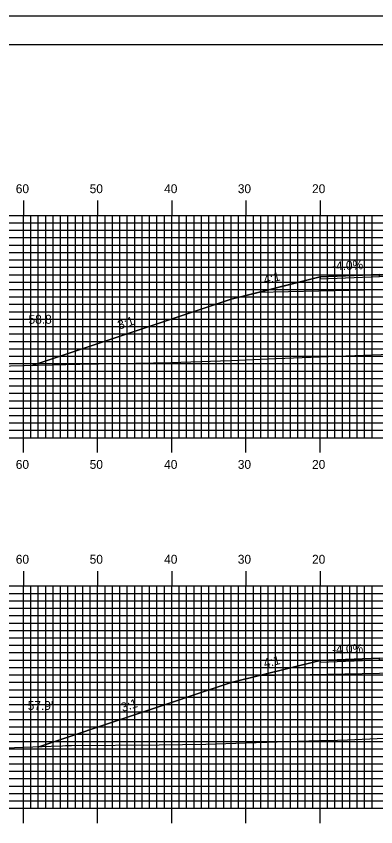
# Model space of a CAD drawing. Extents: x 1788156 to 1788500, y 442591 to 442811.
# Drawn here: x 1788261.2 to 1788309.6, y 442701.2 to 442810.5 of the extents above; entities that cross this region are included whole.
import ezdxf

# ---------------------------------------------------------------- set-up
doc = ezdxf.new("R2010")
doc.units = 0
for name, color, linetype in [('ANNOTATION', 7, 'Continuous'), ('BORDER', 7, 'Continuous'), ('D_Roadway_Centerline', 7, 'Continuous'), ('D_Roadway_Edge_Shoulder', 7, 'Continuous'), ('D_Roadway_SlopeLines', 7, 'Continuous'), ('D_Roadway_SubGrade', 7, 'Continuous'), ('D_Text_Standard', 7, 'Continuous'), ('H_V ANNOTATION', 7, 'Continuous'), ('MAJOR', 7, 'Continuous'), ('MINOR', 7, 'Continuous'), ('PLOT BOUNDARY', 7, 'Continuous'), ('S_Roadway_Centerline', 7, 'Continuous')]:
    doc.layers.add(name, color=color, linetype=linetype)

msp = doc.modelspace()

# ---------------------------------------------------------------- linework, layer by layer
at = {"layer": 'BORDER'}
msp.add_lwpolyline([(1788172.53, 442596.67), (1788492.53, 442596.67), (1788492.53, 442806.67), (1788172.53, 442806.67)], close=True, dxfattribs=at)
at = {"layer": 'D_Roadway_Centerline'}
for points in [[(1788263.31, 442763.43), (1788290.13, 442772.37), (1788293.77, 442773.28), (1788302.13, 442775.37), (1788310.13, 442775.69), (1788322.13, 442775.96), (1788334.13, 442776.22), (1788342.13, 442775.9), (1788350.49, 442773.81), (1788354.13, 442772.9), (1788371.39, 442767.15)], [(1788264.21, 442711.98), (1788290.13, 442720.62), (1788293.77, 442721.53), (1788302.13, 442723.62), (1788310.13, 442723.94), (1788322.13, 442724.21), (1788334.13, 442724.47), (1788342.13, 442724.15), (1788350.49, 442722.06), (1788354.13, 442721.15), (1788372.38, 442715.07)]]:
    msp.add_lwpolyline(points, dxfattribs=at)
at = {"layer": 'D_Roadway_Edge_Shoulder'}
for points in [[(1788310.13, 442775.69), (1788302.13, 442775.37), (1788302.13, 442775.12), (1788310.13, 442775.44)], [(1788310.13, 442723.94), (1788302.13, 442723.62), (1788302.13, 442723.37), (1788310.13, 442723.69)]]:
    msp.add_lwpolyline(points, close=True, dxfattribs=at)
at = {"layer": 'D_Roadway_SlopeLines'}
for points in [[(1788302.13, 442775.37), (1788290.13, 442772.37), (1788263.31, 442763.43)], [(1788302.13, 442723.62), (1788290.13, 442720.62), (1788264.21, 442711.98)]]:
    msp.add_lwpolyline(points, dxfattribs=at)
at = {"layer": 'D_Roadway_SubGrade'}
for points in [[(1788310.13, 442773.61), (1788293.77, 442773.28), (1788302.13, 442775.37), (1788302.13, 442775.12), (1788310.13, 442775.44), (1788322.13, 442775.71), (1788334.13, 442775.97), (1788342.13, 442775.65), (1788342.13, 442775.9), (1788350.49, 442773.81), (1788334.13, 442774.14), (1788322.13, 442773.87)], [(1788310.13, 442721.86), (1788293.77, 442721.53), (1788302.13, 442723.62), (1788302.13, 442723.37), (1788310.13, 442723.69), (1788322.13, 442723.96), (1788334.13, 442724.22), (1788342.13, 442723.9), (1788342.13, 442724.15), (1788350.49, 442722.06), (1788334.13, 442722.39), (1788322.13, 442722.12)]]:
    msp.add_lwpolyline(points, close=True, dxfattribs=at)
at = {"layer": 'MAJOR'}
for p, q in [((1788262.13, 442785.67), (1788262.13, 442783.67)), ((1788272.13, 442785.67), (1788272.13, 442783.67)), ((1788282.13, 442785.67), (1788282.13, 442783.67)), ((1788292.13, 442785.67), (1788292.13, 442783.67)), ((1788302.13, 442785.67), (1788302.13, 442783.67)), ((1788182.13, 442783.67), (1788462.13, 442783.67)), ((1788182.13, 442783.67), (1788462.13, 442783.67)), ((1788262.13, 442753.67), (1788262.13, 442783.67)), ((1788272.13, 442753.67), (1788272.13, 442783.67)), ((1788282.13, 442753.67), (1788282.13, 442783.67)), ((1788292.13, 442753.67), (1788292.13, 442783.67)), ((1788302.13, 442753.67), (1788302.13, 442783.67)), ((1788182.13, 442778.67), (1788462.13, 442778.67)), ((1788182.13, 442773.67), (1788462.13, 442773.67)), ((1788182.13, 442768.67), (1788462.13, 442768.67)), ((1788182.13, 442763.67), (1788462.13, 442763.67)), ((1788182.13, 442758.67), (1788462.13, 442758.67)), ((1788182.13, 442753.67), (1788462.13, 442753.67)), ((1788182.13, 442753.67), (1788462.13, 442753.67)), ((1788262.13, 442751.66), (1788262.13, 442753.67)), ((1788272.13, 442751.66), (1788272.13, 442753.67)), ((1788282.13, 442751.66), (1788282.13, 442753.67)), ((1788292.13, 442751.66), (1788292.13, 442753.67)), ((1788302.13, 442751.66), (1788302.13, 442753.67)), ((1788262.13, 442735.67), (1788262.13, 442733.67)), ((1788272.13, 442735.67), (1788272.13, 442733.67)), ((1788282.13, 442735.67), (1788282.13, 442733.67)), ((1788292.13, 442735.67), (1788292.13, 442733.67)), ((1788302.13, 442735.67), (1788302.13, 442733.67)), ((1788182.13, 442733.67), (1788462.13, 442733.67)), ((1788182.13, 442733.67), (1788462.13, 442733.67)), ((1788262.13, 442703.67), (1788262.13, 442733.67)), ((1788272.13, 442703.67), (1788272.13, 442733.67)), ((1788282.13, 442703.67), (1788282.13, 442733.67)), ((1788292.13, 442703.67), (1788292.13, 442733.67)), ((1788302.13, 442703.67), (1788302.13, 442733.67)), ((1788182.13, 442728.67), (1788462.13, 442728.67)), ((1788182.13, 442723.67), (1788462.13, 442723.67)), ((1788182.13, 442718.67), (1788462.13, 442718.67)), ((1788182.13, 442713.67), (1788462.13, 442713.67)), ((1788182.13, 442708.67), (1788462.13, 442708.67)), ((1788182.13, 442703.67), (1788462.13, 442703.67)), ((1788182.13, 442703.67), (1788462.13, 442703.67)), ((1788262.13, 442701.66), (1788262.13, 442703.67)), ((1788272.13, 442701.66), (1788272.13, 442703.67)), ((1788282.13, 442701.66), (1788282.13, 442703.67)), ((1788292.13, 442701.66), (1788292.13, 442703.67)), ((1788302.13, 442701.66), (1788302.13, 442703.67))]:
    msp.add_line(p, q, dxfattribs=at)
at = {"layer": 'MINOR'}
for p, q in [((1788263.13, 442753.67), (1788263.13, 442783.67)), ((1788264.13, 442753.67), (1788264.13, 442783.67)), ((1788265.13, 442753.67), (1788265.13, 442783.67)), ((1788266.13, 442753.67), (1788266.13, 442783.67)), ((1788267.13, 442753.67), (1788267.13, 442783.67)), ((1788268.13, 442753.67), (1788268.13, 442783.67)), ((1788269.13, 442753.67), (1788269.13, 442783.67)), ((1788270.13, 442753.67), (1788270.13, 442783.67)), ((1788271.13, 442753.67), (1788271.13, 442783.67)), ((1788273.13, 442753.67), (1788273.13, 442783.67)), ((1788274.13, 442753.67), (1788274.13, 442783.67)), ((1788275.13, 442753.67), (1788275.13, 442783.67)), ((1788276.13, 442753.67), (1788276.13, 442783.67)), ((1788277.13, 442753.67), (1788277.13, 442783.67)), ((1788278.13, 442753.67), (1788278.13, 442783.67)), ((1788279.13, 442753.67), (1788279.13, 442783.67)), ((1788280.13, 442753.67), (1788280.13, 442783.67)), ((1788281.13, 442753.67), (1788281.13, 442783.67)), ((1788283.13, 442753.67), (1788283.13, 442783.67)), ((1788284.13, 442753.67), (1788284.13, 442783.67)), ((1788285.13, 442753.67), (1788285.13, 442783.67)), ((1788286.13, 442753.67), (1788286.13, 442783.67)), ((1788287.13, 442753.67), (1788287.13, 442783.67)), ((1788288.13, 442753.67), (1788288.13, 442783.67)), ((1788289.13, 442753.67), (1788289.13, 442783.67)), ((1788290.13, 442753.67), (1788290.13, 442783.67)), ((1788291.13, 442753.67), (1788291.13, 442783.67)), ((1788293.13, 442753.67), (1788293.13, 442783.67)), ((1788294.13, 442753.67), (1788294.13, 442783.67)), ((1788295.13, 442753.67), (1788295.13, 442783.67)), ((1788296.13, 442753.67), (1788296.13, 442783.67)), ((1788297.13, 442753.67), (1788297.13, 442783.67)), ((1788298.13, 442753.67), (1788298.13, 442783.67)), ((1788299.13, 442753.67), (1788299.13, 442783.67)), ((1788300.13, 442753.67), (1788300.13, 442783.67)), ((1788301.13, 442753.67), (1788301.13, 442783.67)), ((1788303.13, 442753.67), (1788303.13, 442783.67)), ((1788304.13, 442753.67), (1788304.13, 442783.67)), ((1788305.13, 442753.67), (1788305.13, 442783.67)), ((1788306.13, 442753.67), (1788306.13, 442783.67)), ((1788307.13, 442753.67), (1788307.13, 442783.67)), ((1788308.13, 442753.67), (1788308.13, 442783.67)), ((1788309.13, 442753.67), (1788309.13, 442783.67)), ((1788182.13, 442782.67), (1788462.13, 442782.67)), ((1788182.13, 442781.67), (1788462.13, 442781.67)), ((1788182.13, 442780.67), (1788462.13, 442780.67)), ((1788182.13, 442779.67), (1788462.13, 442779.67)), ((1788182.13, 442777.67), (1788462.13, 442777.67)), ((1788182.13, 442776.67), (1788462.13, 442776.67)), ((1788182.13, 442775.67), (1788462.13, 442775.67)), ((1788182.13, 442774.67), (1788462.13, 442774.67)), ((1788182.13, 442772.67), (1788462.13, 442772.67)), ((1788182.13, 442771.67), (1788462.13, 442771.67)), ((1788182.13, 442770.67), (1788462.13, 442770.67)), ((1788182.13, 442769.67), (1788462.13, 442769.67)), ((1788182.13, 442767.67), (1788462.13, 442767.67)), ((1788182.13, 442766.67), (1788462.13, 442766.67)), ((1788182.13, 442765.67), (1788462.13, 442765.67)), ((1788182.13, 442764.67), (1788462.13, 442764.67)), ((1788182.13, 442762.67), (1788462.13, 442762.67)), ((1788182.13, 442761.67), (1788462.13, 442761.67)), ((1788182.13, 442760.67), (1788462.13, 442760.67)), ((1788182.13, 442759.67), (1788462.13, 442759.67)), ((1788182.13, 442757.67), (1788462.13, 442757.67)), ((1788182.13, 442756.67), (1788462.13, 442756.67)), ((1788182.13, 442755.67), (1788462.13, 442755.67)), ((1788182.13, 442754.67), (1788462.13, 442754.67)), ((1788263.13, 442703.67), (1788263.13, 442733.67)), ((1788264.13, 442703.67), (1788264.13, 442733.67)), ((1788265.13, 442703.67), (1788265.13, 442733.67)), ((1788266.13, 442703.67), (1788266.13, 442733.67)), ((1788267.13, 442703.67), (1788267.13, 442733.67)), ((1788268.13, 442703.67), (1788268.13, 442733.67)), ((1788269.13, 442703.67), (1788269.13, 442733.67)), ((1788270.13, 442703.67), (1788270.13, 442733.67)), ((1788271.13, 442703.67), (1788271.13, 442733.67)), ((1788273.13, 442703.67), (1788273.13, 442733.67)), ((1788274.13, 442703.67), (1788274.13, 442733.67)), ((1788275.13, 442703.67), (1788275.13, 442733.67)), ((1788276.13, 442703.67), (1788276.13, 442733.67)), ((1788277.13, 442703.67), (1788277.13, 442733.67)), ((1788278.13, 442703.67), (1788278.13, 442733.67)), ((1788279.13, 442703.67), (1788279.13, 442733.67)), ((1788280.13, 442703.67), (1788280.13, 442733.67)), ((1788281.13, 442703.67), (1788281.13, 442733.67)), ((1788283.13, 442703.67), (1788283.13, 442733.67)), ((1788284.13, 442703.67), (1788284.13, 442733.67)), ((1788285.13, 442703.67), (1788285.13, 442733.67)), ((1788286.13, 442703.67), (1788286.13, 442733.67)), ((1788287.13, 442703.67), (1788287.13, 442733.67)), ((1788288.13, 442703.67), (1788288.13, 442733.67)), ((1788289.13, 442703.67), (1788289.13, 442733.67)), ((1788290.13, 442703.67), (1788290.13, 442733.67)), ((1788291.13, 442703.67), (1788291.13, 442733.67)), ((1788293.13, 442703.67), (1788293.13, 442733.67)), ((1788294.13, 442703.67), (1788294.13, 442733.67)), ((1788295.13, 442703.67), (1788295.13, 442733.67)), ((1788296.13, 442703.67), (1788296.13, 442733.67)), ((1788297.13, 442703.67), (1788297.13, 442733.67)), ((1788298.13, 442703.67), (1788298.13, 442733.67)), ((1788299.13, 442703.67), (1788299.13, 442733.67)), ((1788300.13, 442703.67), (1788300.13, 442733.67)), ((1788301.13, 442703.67), (1788301.13, 442733.67)), ((1788303.13, 442703.67), (1788303.13, 442733.67)), ((1788304.13, 442703.67), (1788304.13, 442733.67)), ((1788305.13, 442703.67), (1788305.13, 442733.67)), ((1788306.13, 442703.67), (1788306.13, 442733.67)), ((1788307.13, 442703.67), (1788307.13, 442733.67)), ((1788308.13, 442703.67), (1788308.13, 442733.67)), ((1788309.13, 442703.67), (1788309.13, 442733.67)), ((1788182.13, 442732.67), (1788462.13, 442732.67)), ((1788182.13, 442731.67), (1788462.13, 442731.67)), ((1788182.13, 442730.67), (1788462.13, 442730.67)), ((1788182.13, 442729.67), (1788462.13, 442729.67)), ((1788182.13, 442727.67), (1788462.13, 442727.67)), ((1788182.13, 442726.67), (1788462.13, 442726.67)), ((1788182.13, 442725.67), (1788462.13, 442725.67)), ((1788182.13, 442724.67), (1788462.13, 442724.67)), ((1788182.13, 442722.67), (1788462.13, 442722.67)), ((1788182.13, 442721.67), (1788462.13, 442721.67)), ((1788182.13, 442720.67), (1788462.13, 442720.67)), ((1788182.13, 442719.67), (1788462.13, 442719.67)), ((1788182.13, 442717.67), (1788462.13, 442717.67)), ((1788182.13, 442716.67), (1788462.13, 442716.67)), ((1788182.13, 442715.67), (1788462.13, 442715.67)), ((1788182.13, 442714.67), (1788462.13, 442714.67)), ((1788182.13, 442712.67), (1788462.13, 442712.67)), ((1788182.13, 442711.67), (1788462.13, 442711.67)), ((1788182.13, 442710.67), (1788462.13, 442710.67)), ((1788182.13, 442709.67), (1788462.13, 442709.67)), ((1788182.13, 442707.67), (1788462.13, 442707.67)), ((1788182.13, 442706.67), (1788462.13, 442706.67)), ((1788182.13, 442705.67), (1788462.13, 442705.67)), ((1788182.13, 442704.67), (1788462.13, 442704.67))]:
    msp.add_line(p, q, dxfattribs=at)
at = {"layer": 'PLOT BOUNDARY'}
msp.add_lwpolyline([(1788156.34, 442590.55), (1788496.34, 442590.55), (1788496.34, 442810.55), (1788156.34, 442810.55)], close=True, dxfattribs=at)
at = {"layer": 'S_Roadway_Centerline'}
for points in [[(1788258.44, 442763.31), (1788269.72, 442763.6), (1788277.29, 442763.73), (1788282, 442763.84), (1788290.04, 442764.11), (1788296.2, 442764.34), (1788304.41, 442764.68), (1788315.1, 442765.1), (1788318.07, 442765.22), (1788323.51, 442765.34), (1788330.14, 442765.54), (1788333.79, 442765.63), (1788347, 442766.11), (1788352.31, 442766.28), (1788356.42, 442766.47), (1788371.24, 442767.14), (1788390.29, 442767.78)], [(1788248.55, 442711.4), (1788265.85, 442712.05), (1788267.39, 442712.11), (1788267.82, 442712.13), (1788268.62, 442712.13), (1788280.42, 442712.25), (1788286.71, 442712.34), (1788292.1, 442712.51), (1788302, 442712.8), (1788304.47, 442712.87), (1788305.8, 442712.92), (1788310.82, 442713.13), (1788324.76, 442713.79), (1788328.49, 442713.85), (1788335.13, 442714.01), (1788340.54, 442714.11), (1788343.53, 442714.21), (1788352.35, 442714.24), (1788362.21, 442714.61), (1788368.07, 442714.91), (1788381.28, 442715.39)]]:
    msp.add_lwpolyline(points, dxfattribs=at)

# ---------------------------------------------------------------- texts
at = {"layer": 'ANNOTATION'}
for s, rotation, p in [('-4.0%', 2.2906, (1788303.76, 442776.24)), ('4:1', 14.0362, (1788294.67, 442774.37)), ('3:1', 18.4348, (1788275.06, 442768.26)), ('-4.0%', 2.2906, (1788303.76, 442724.49)), ('4:1', 14.0362, (1788294.67, 442722.62)), ('3:1', 18.4348, (1788275.51, 442716.66))]:
    msp.add_text(s, height=1.2, rotation=rotation, dxfattribs=at).set_placement(p)
at = {"layer": 'D_Text_Standard'}
for s, p in [("58.8'", (1788262.82, 442769.05)), ("57.9'", (1788262.71, 442716.94))]:
    msp.add_text(s, height=1.2, dxfattribs=at).set_placement(p)
at = {"layer": 'H_V ANNOTATION'}
for s, p in [('60', (1788261.1, 442786.67)), ('50', (1788271.06, 442786.67)), ('40', (1788281.1, 442786.67)), ('30', (1788291.03, 442786.67)), ('20', (1788301.04, 442786.67)), ('60', (1788261.1, 442749.47)), ('50', (1788271.06, 442749.47)), ('40', (1788281.1, 442749.47)), ('30', (1788291.03, 442749.47)), ('20', (1788301.04, 442749.47)), ('60', (1788261.1, 442736.67)), ('50', (1788271.06, 442736.67)), ('40', (1788281.1, 442736.67)), ('30', (1788291.03, 442736.67)), ('20', (1788301.04, 442736.67))]:
    msp.add_text(s, height=1.2, dxfattribs=at).set_placement(p)

doc.saveas('drawing.dxf')
